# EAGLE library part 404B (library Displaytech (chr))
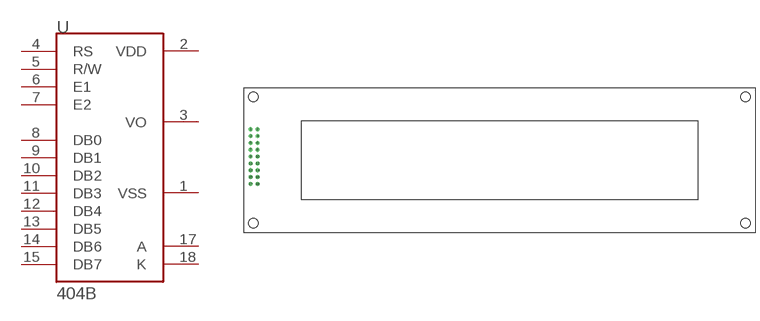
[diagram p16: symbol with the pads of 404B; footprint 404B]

Designator prefix -

## 404B  [404B]
1  VSS  pwr
2  VDD  pwr
3  VO  in
4  RS
5  R/W
6  E1
7  E2
8  DB0
9  DB1
10  DB2
11  DB3
12  DB4
13  DB5
14  DB6
15  DB7
17  A  pwr
18  K  pwr

## Footprint 404B (pad centres in mm)
drill 1.016 round: 1 0,0; 2 2.54,0; 3 0,-2.54; 4 2.54,-2.54; 5 0,-5.08; 6 2.54,-5.08; 7 0,-7.62; 8 2.54,-7.62; 9 0,-10.16; 10 2.54,-10.16; 11 0,-12.7; 12 2.54,-12.7; 13 0,-15.24; 14 2.54,-15.24; 15 0,-17.78; 16 2.54,-17.78; 17 0,-20.32; 18 2.54,-20.32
